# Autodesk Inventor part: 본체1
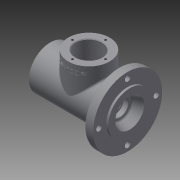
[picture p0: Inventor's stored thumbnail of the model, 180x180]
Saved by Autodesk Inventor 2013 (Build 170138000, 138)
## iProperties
Created: 2016-08
Part Number: 본체1
Material: 일반
Document SubType Name: Modeling
Designer: Administrator
Density: 1 g/cm^3
Author: Administrator
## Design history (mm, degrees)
sketch "스케치1"
  geometry: L1 (0, 0)-(115, 0); L2 (0, 0)-(0, 31); L3 (0, 31)-(99, 31); L4 (99, 31)-(99, 50); L5 (99, 50)-(112, 50); L6 (112, 50)-(112, 31); L7 (112, 31)-(115, 31); L8 (115, 0)-(115, 31)
  constraints: 16 end point, 4 horizontal, 4 vertical
  dimensions: "d0" = 115 distance of L1.start L1.end; "d1" = 62 diameter of L7 L1; "d2" = 100 diameter of L5 L1; "d3" = 62 diameter of L3 L1; "d4" = 13 distance between parallel lines of L6 L4; "d5" = 3 distance between parallel lines of L8 L6
revolve "회전1" sketch "스케치1" stored, may be unused: angle "d6" = 90 deg
sketch "스케치2"
  geometry: L1 (0, -31)-(0, 31) reference; L2 (115, -31)-(115, 31) reference; L3 (9, 0)-(9, 24); L4 (9, 24)-(12, 24); L5 (12, 24)-(12, 0); L6 (12, 20)-(21, 20); L7 (21, 20)-(21, 0); L8 (21, 17.5)-(25.003, 17.5); L9 (25.003, 17.5)-(25.003, 0); L10 (25.003, 18.5)-(26.753, 18.5); L11 (26.753, 18.5)-(26.753, 0); L12 (26.753, 18.5)-(26.753, 17.5); L13 (26.753, 17.5)-(37, 17.5); L14 (37, 17.5)-(37, 0); L15 (37, 17.5)-(37, 26); L16 (37, 26)-(75, 26); L17 (75, 26)-(75, 0); L18 (75, 17.5)-(86, 17.5); L19 (86, 17.5)-(86, 0); L20 (86, 16.5)-(91, 16.5); L21 (91, 16.5)-(91, 0); L22 (91, 10)-(93.7, 10); L23 (93.7, 10)-(93.7, 0); L24 (101, 16)-(115, 21); L25 (115, 21)-(115, 0); L26 (93.7, 12.5)-(101, 12.5); L27 (101, 12.5)-(101, 16); L28 (101, 12.5)-(101, 0); L29 (25.003, 17.5)-(25.003, 18.5); L30 (93.7, 10)-(93.7, 12.5); L31 (0, 31)-(99, 31) reference; L32 (0, 33.865)-(56, 33.865); L33 (56, 33.865)-(56, 16); L34 (0, 31)-(0, 33.865); 1 further point
  constraints: 62 end point, 19 vertical, 10 horizontal, 8 point on line, 1 midpoint, 15 other
  dimensions: "d7" = 48 dimension on L4; "d9" = 40 dimension on L6; "d10" = 35 dimension on L8; "d11" = 35 dimension on L13; "d12" = 37 dimension on L10; "d13" = 52 dimension on L16; "d14" = 35 dimension on L18; "d15" = 33 dimension on L20; "d17" = 20 dimension on L22; "d20" = 42 dimension on L24.end; "d22" = 25 dimension on L26; "d23" = 32 dimension on L24.start; "d24" = 14 distance between parallel lines of L2 L27; "d25" = 3 distance between parallel lines of L5 L3; "d26" = 21 distance between parallel lines of L7 L1; "d27" = 12 distance between parallel lines of L5 L1; "d29" = 26.7525 distance between parallel lines of L1 L11; "d30" = 1.75 distance of L10.start L10.end; "d31" = 38 distance between parallel lines of L17 L14; "d32" = 86 distance between parallel lines of L1 L19; "d33" = 7.3 distance between parallel lines of L27 L23; "d34" = 2.7 distance between parallel lines of L23 L21; "d95" = 56 distance of L32.start L32.end
revolve "회전2" sketch "스케치2" stored, may be unused: angle "d35" = 90 deg
hole "구멍1" diameter "d38" = 40.376; stored, may be unused: countersink angle "d42" = 90 deg, drill point angle "d44" = 0 deg; dims "d36" = 10, "d37" = 10, "d39" = 6, "d40" = 4, "d41" = 2, "d43" = 9
node "작업 평면1"
sketch "스케치3"
  geometry: L1 (-105.5, -31)-(-105.5, 31) reference; L2 (-105.5, 0)-(-49.5, 0); C1 r 30 at (-49.5, 0)
  constraints: 2 end point, 1 centre point, 1 coincident, 1 horizontal
  dimensions: "d45" = 56 distance of L2.start L2.end; "d46" = 60 diameter of C1
extrude "돌출1" join sketch "스케치3" stored distance "d47" = 10; taper "d48" = 0 deg
hole "구멍2" diameter "d51" = 38; stored, may be unused: countersink angle "d55" = 90 deg, drill point angle "d57" = 0 deg; dims "d49" = 10, "d50" = 10, "d52" = 6, "d53" = 4, "d54" = 2, "d56" = 9
sketch "스케치4" dims "d58" = 48
  geometry: L1 (0, 0)-(0, 24); C1 r 19 at (0, 0) reference; C2 r 30 at (0, 0) reference; 2 further points
  constraints: 2 coincident, 2 end point, 1 vertical, 1 vertical alignment, 2 other
hole "구멍3" sketch "스케치4" at (0, 24) diameter "d59" = 3.242; stored, may be unused: countersink angle "d63" = 90 deg, drill point angle "d65" = 0 deg; dims "d60" = 8, "d61" = 4, "d62" = 2, "d64" = 10
sketch "스케치5" dims "d69" = 83
  geometry: L1 (0, 0)-(0, 41.5); C1 r 31 at (0, 0) reference; C2 r 50 at (0, 0) reference; 2 further points
  constraints: 2 coincident, 2 end point, 1 vertical, 1 vertical alignment, 2 other
hole "구멍4" sketch "스케치5" at (0, 41.5) diameter "d70" = 8; stored, may be unused: countersink angle "d74" = 90 deg, drill point angle "d76" = 0 deg; dims "d71" = 8, "d72" = 4, "d73" = 2, "d75" = 10
fillet "모깎기1" dims "d80" = 3
fillet "모깎기2" dims "d81" = 3
fillet "모깎기3" dims "d82" = 0.3
chamfer "모따기1" distance "d83" = 0.7; stored, may be unused: second distance "d84" = 2, angle "d85" = 30 deg
chamfer "모따기2" distance "d86" = 1; stored, may be unused: second distance "d87" = 2, angle "d88" = 45 deg
node "작업 평면2"
sketch "스케치6"
  geometry: L1 (-30, 0)-(30, 0) reference; L2 (0, 0)-(0, -10); L3 (-20.739, -6.998)-(20.739, -6.998); L4 (20.739, -6.998)-(20.739, -13.002); L5 (20.739, -13.002)-(-20.739, -13.002); L6 (-20.739, -13.002)-(-20.739, -6.998); L7 (-20.739, -13.002)-(20.739, -6.998); 1 further point
  constraints: 4 end point, 2 midpoint, 1 vertical, 2 other
  dimensions: "d89" = 10 distance of L2.end L2.start
feature "엠보싱1" sketch "스케치6" dims "d0" = 115, "d1" = 62, "d2" = 100, "d3" = 62, "d4" = 13, "d5" = 3, "d90" = 0.5, "d91" = 0
chamfer "모따기3" distance "d92" = 1; stored, may be unused: second distance "d93" = 2, angle "d94" = 45 deg
node "솔리드1"
pattern_circular "원형 패턴1" dims angle "d67" = 360 deg
pattern_circular "원형 패턴2" dims angle "d78" = 360 deg
node "투영된 루프1"
node "투영된 루프2"
